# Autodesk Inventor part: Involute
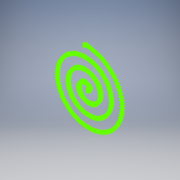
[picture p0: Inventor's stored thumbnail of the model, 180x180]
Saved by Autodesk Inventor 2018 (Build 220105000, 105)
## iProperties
Created: 2008-02
Part Number: Involute
Document SubType Name: Modeling
Designer: Autodesk, Inc.
Density: 1 g/cm^3
Material: Generic
Appearance: Default
Author: Autodesk, Inc.
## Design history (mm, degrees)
sketch "Sketch1"
  geometry: 300 further points
  constraints: 300 other
